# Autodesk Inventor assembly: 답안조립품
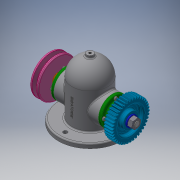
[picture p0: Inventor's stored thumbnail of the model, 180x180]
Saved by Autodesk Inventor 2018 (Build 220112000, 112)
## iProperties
Created: 2019-11
Part Number: 답안조립품
Material: 일반
Document SubType Name: Assembly
Designer: USER
Author: USER
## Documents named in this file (14)
- C:\Users\USER\Desktop\491104V1045\답안조립품.iam
- C:\Users\USER\Desktop\491104V1045\본체.ipt
- C:\Users\USER\Desktop\491104V1045\V-벨트풀리.ipt
- V-벨트풀리.ipt
- C:\Users\USER\Desktop\491104V1045\너트 M12x1.25.ipt
- C:\Users\USER\Desktop\491104V1045\베어링 6203.ipt
- C:\Users\USER\Desktop\491104V1045\볼트 M4.ipt
- C:\Users\USER\Desktop\491104V1045\부시.ipt
- C:\Users\USER\Desktop\491104V1045\스퍼기어.ipt
- C:\Users\USER\Desktop\491104V1045\오일 실 26 38 8.ipt
- C:\Users\USER\Desktop\491104V1045\와셔 12x24.ipt
- C:\Users\USER\Desktop\491104V1045\축.ipt
- C:\Users\USER\Desktop\491104V1045\커버.ipt
- C:\Users\USER\Desktop\491104V1045\키 5x5x12.ipt
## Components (1 placed, 1 different names)
1. V-벨트풀리:1
